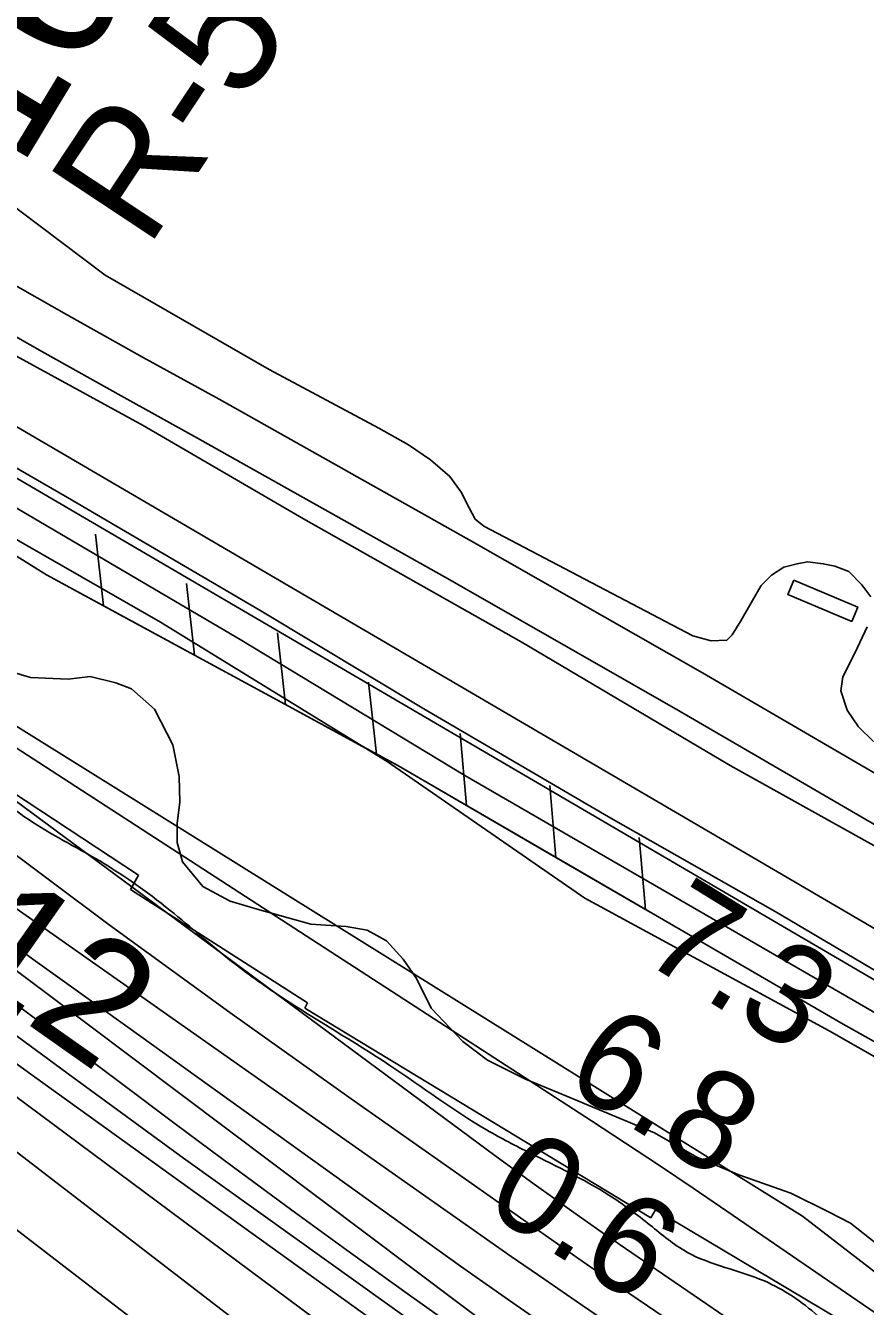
# Model space of a CAD drawing. Extents: x 3734862 to 3772949, y 391520 to 417239.
# Drawn here: x 3764747 to 3765314, y 398025 to 398891 of the extents above; entities that cross this region are included whole.
import ezdxf

# ---------------------------------------------------------------- set-up
doc = ezdxf.new("R2010")
doc.units = 0
for name, color, linetype in [('V-BLDG-OTLN', 7, 'Continuous'), ('V-FLOD-BASE', 7, 'Continuous'), ('V-LEVE-TOET', 7, 'Continuous'), ('V-RIVR-EDGE', 7, 'Continuous'), ('V-RIVR-IDEN', 7, 'Continuous'), ('V-RIVR-RANG', 7, 'Continuous'), ('V-RIVR-RANG-IDEN', 7, 'Continuous'), ('V-ROAD-CNTR', 7, 'Continuous'), ('V-RRAP-FSHR', 7, 'Continuous'), ('V-RRAP-RVMT', 7, 'Continuous'), ('V-SITE-VEGE', 7, 'Continuous'), ('V-SURV-IDEN', 7, 'Continuous'), ('V-SURV-LINE', 7, 'Continuous'), ('V-TOPO-DPTH', 7, 'Continuous'), ('V-TOPO-MAJR', 7, 'Continuous'), ('V-TOPO-MINR', 7, 'Continuous'), ('V-TOPO-WATR', 7, 'Continuous')]:
    doc.layers.add(name, color=color, linetype=linetype)

msp = doc.modelspace()

# ---------------------------------------------------------------- linework, layer by layer
at = {"layer": 'V-BLDG-OTLN'}
msp.add_lwpolyline([(3765265.95, 398515.86), (3765309.25, 398497.52), (3765305.19, 398487.94), (3765261.9, 398506.28)], close=True, dxfattribs=at)
at = {"layer": 'V-FLOD-BASE'}
msp.add_lwpolyline([(3765919.69, 397923.87), (3765784.81, 397985.29), (3765736.12, 398012.21), (3765619.99, 398078.34), (3765504.44, 398146.23), (3765380.1, 398217.04), (3765253.41, 398291.96), (3765140.8, 398355.75), (3765015.87, 398428.9), (3764905.59, 398495.04), (3764774.8, 398571.71), (3764644, 398647.2), (3764560.13, 398694.61), (3764527.87, 398714.51), (3764496.78, 398740.27), (3764392.35, 398828.69), (3764326.64, 398884.32), (3764321.95, 398887.24), (3764318.43, 398888.41), (3764313.74, 398888.41), (3764307.88, 398886.64)], dxfattribs=at)
at = {"layer": 'V-LEVE-TOET'}
for points in [[(3765336.26, 398214.64), (3765176.14, 398307.1), (3765043.58, 398383.77), (3764891.67, 398475.66), (3764737.41, 398566.38), (3764574.94, 398662.36), (3764493.99, 398717.39), (3764439.43, 398761.3), (3764323.27, 398859.67), (3764308.02, 398870.21), (3764290.2, 398882.28), (3764276.7, 398899.85), (3764221.55, 398947.28), (3764113.59, 399048), (3763978.07, 399156.91), (3763854.3, 399242.38), (3763724.66, 399337.81), (3763588.56, 399436.16), (3763446.02, 399536.27), (3763304.06, 399635.79)], [(3764703.96, 398687.18), (3764825.96, 398620.47), (3764934.47, 398557.26), (3765081.68, 398474.16), (3765223.04, 398390.47), (3765371.43, 398307.96), (3765509.86, 398218.4), (3765656.5, 398127.67), (3765782.02, 398053.35), (3765894.62, 397998.94)]]:
    msp.add_lwpolyline(points, dxfattribs=at)
at = {"layer": 'V-RIVR-EDGE'}
msp.add_spline([(3755702.08, 404495.32), (3755757.18, 404470.77), (3755793.3, 404451.23), (3755852.47, 404424.41), (3755881.39, 404415.75), (3755906.23, 404404.38), (3755920.22, 404395.76), (3755948.67, 404379.41), (3755958.16, 404378.93), (3755969.01, 404378), (3755990.69, 404368.45), (3756022.75, 404350.29), (3756054.82, 404336.64), (3756079.66, 404323.02), (3756103.59, 404309.39), (3756144.23, 404288.04), (3756167.69, 404268.99), (3756188.91, 404253.57), (3756231.36, 404233.11), (3756271.56, 404217.19), (3756299.11, 404203.1), (3756403.01, 404163.51), (3756460.37, 404140.31), (3756508.69, 404114.87), (3756530.82, 404103.96), (3756588.18, 404078.04), (3756639.21, 404052.15), (3756694.29, 404019.45), (3756726.8, 403998.12), (3756735.82, 403989.06), (3756740.32, 403979.55), (3756740.3, 403973.22), (3756740.74, 403967.79), (3756747.5, 403960.54), (3756759.69, 403953.73), (3756786.34, 403941.46), (3756814.34, 403929.18), (3756864.47, 403904.64), (3756889.32, 403895.98), (3756899.72, 403897.32), (3756908.33, 403901.82), (3756919.18, 403901.34), (3756933.18, 403894.07), (3756945.83, 403892.68), (3756956.23, 403893.11), (3756962.12, 403897.16), (3756970.71, 403896.69), (3756978.39, 403894.41), (3756992.41, 403894.83), (3757002.82, 403897.51), (3757019.1, 403901.54), (3757027.7, 403901.52), (3757034.02, 403901.05), (3757036.27, 403896.53), (3757036.71, 403891.1), (3757038.5, 403883.41), (3757046.62, 403874.34), (3757060.62, 403866.17), (3757076.41, 403853.92), (3757104.39, 403831.25), (3757122.44, 403816.73), (3757145.47, 403804.47), (3757165.34, 403796.73), (3757181.6, 403787.2), (3757194.24, 403777.67), (3757213.65, 403765.41), (3757229.9, 403756.33), (3757251.58, 403745.88), (3757266.49, 403741.32), (3757283.2, 403734.49), (3757308.94, 403720.87), (3757360.42, 403694.06), (3757393.83, 403670.92), (3757429.96, 403657.26), (3757461.59, 403645.43), (3757505.4, 403628.14), (3757548.31, 403610.4), (3757591.66, 403587.23), (3757649.45, 403552.27), (3757711.75, 403512.78), (3757753.76, 403493.23), (3757766.86, 403487.78), (3757773.19, 403487.76), (3757785.86, 403494.06), (3757794.45, 403494.04), (3757803.49, 403489.49), (3757807.08, 403480.89), (3757810.64, 403456.02), (3757814.23, 403447.87), (3757826.42, 403436.99), (3757854.41, 403422.9), (3757930.26, 403373.88), (3757975.85, 403342.57), (3758005.19, 403323.5), (3758062.07, 403286.74), (3758092.31, 403263.6), (3758175.82, 403209.59), (3758234.51, 403169.2), (3758283.7, 403133.81), (3758328.84, 403103.41), (3758399.23, 403041.74), (3758421.79, 403023.15), (3758438.05, 403017.68), (3758463.83, 403017.62), (3758491.43, 403026.14), (3758504.53, 403022.04), (3758513.56, 403014.33), (3758513.99, 403006.19), (3758499.95, 402997.18), (3758498.12, 402989.95), (3758502.16, 402978.18), (3758510.73, 402969.57), (3758522.02, 402962.76), (3758545.05, 402948.69), (3758582.07, 402926.89), (3758650.23, 402878.79), (3758697.61, 402840.7), (3758721.52, 402820.29), (3758740.94, 402809.39), (3758782.02, 402784.87), (3758831.24, 402755.36), (3758902.12, 402711.78), (3758960.36, 402675.46), (3759018.58, 402634.62), (3759069.59, 402599.68), (3759134.59, 402553.4), (3759185.57, 402508.06), (3759223.48, 402478.12), (3759262.29, 402448.18), (3759321.41, 402402.37), (3759371.51, 402366.07), (3759431.54, 402323.42), (3759463.59, 402300.28), (3759488.86, 402281.68), (3759576.89, 402222.68), (3759626.99, 402186.84), (3759672.12, 402153.72), (3759778.21, 402087.44), (3759832.83, 402050.68), (3759873, 402019.38), (3759909.55, 401989.45), (3760050.81, 401883.75), (3760100.02, 401850.16), (3760145.61, 401819.31), (3760185.77, 401788.01), (3760211.95, 401766.69), (3760254.82, 401734.48), (3760285.51, 401709.08), (3760303.12, 401700.45), (3760325.25, 401691.35), (3760352.78, 401671.39), (3760391.14, 401641), (3760430.41, 401611.96), (3760461.55, 401590.18), (3760536.95, 401542.97), (3760582.99, 401510.76), (3760602.85, 401495.79), (3760629.02, 401477.18), (3760672.36, 401449.49), (3760711.19, 401426.79), (3760818.61, 401347.85), (3760872.33, 401310.64), (3760925.58, 401271.62), (3760948.6, 401251.67), (3761039.76, 401181.81), (3761107.02, 401135.52), (3761151.7, 401104.67), (3761172.93, 401093.31), (3761186.03, 401090.57), (3761199.15, 401092.79), (3761219.51, 401099.07), (3761228.11, 401099.5), (3761233.52, 401095.42), (3761236.67, 401087.73), (3761236.64, 401077.78), (3761228.47, 401063.78), (3761223.03, 401057.47), (3761223.01, 401049.33), (3761228.86, 401039.37), (3761242.39, 401026.67), (3761254.14, 401021.67), (3761266.79, 401018.47), (3761292.52, 401001.68), (3761317.34, 400980.37), (3761342.15, 400955.44), (3761463.07, 400853.4), (3761509.99, 400812.14), (3761550.15, 400777.68), (3761585.34, 400746.84), (3761681.47, 400674.26), (3761756.4, 400618.91), (3761817.77, 400572.19), (3761878.26, 400530.44), (3761996.49, 400436.55), (3762057.42, 400389.83), (3762104.8, 400352.63), (3762156.25, 400313.17), (3762204.54, 400277.33), (3762245.17, 400247.84), (3762291.65, 400210.19), (3762325.94, 400182.07), (3762356.18, 400159.84), (3762404.02, 400123.55), (3762432.9, 400101.32), (3762455.49, 400091.32), (3762473.53, 400075.9), (3762512.34, 400044.16), (3762551.6, 400012.41), (3762593.58, 399983.82), (3762620.21, 399963.4), (3762661.74, 399937.08), (3762686.57, 399919.83), (3762793.08, 399841.35), (3762834.61, 399812.76), (3762873.44, 399790.05), (3762923.1, 399758.28), (3762956.96, 399737.4), (3762984.05, 399721.5), (3763024.22, 399693.37), (3763075.23, 399657.52), (3763115.86, 399633.91), (3763172.75, 399601.21), (3763228.74, 399568.52), (3763285.17, 399533.57), (3763344.31, 399494.08), (3763398.47, 399455.06), (3763444.06, 399421.04), (3763484.68, 399391.09), (3763603.38, 399303.08), (3763654.82, 399261.81), (3763661.14, 399259.53), (3763667.01, 399254.54), (3763671.96, 399245.04), (3763696.33, 399224.18), (3763722.94, 399200.15), (3763745.5, 399180.2), (3763818.14, 399117.17), (3763841.61, 399099.47), (3763852.45, 399092.21), (3763858.76, 399084.06), (3763874.99, 399067.29), (3763898, 399045.98), (3763924.62, 399023.76), (3763949, 399007.87), (3763970.2, 398987.47), (3764004.03, 398952.57), (3764028.38, 398926.74), (3764056.8, 398899.54), (3764092.88, 398862.37), (3764130.77, 398826.11), (3764147.01, 398811.6), (3764152.86, 398799.83), (3764162.32, 398783.53), (3764173.58, 398768.58), (3764186.67, 398757.24), (3764206.08, 398746.34), (3764226.87, 398742.22), (3764246.29, 398733.58), (3764269.32, 398717.7), (3764284.2, 398703.19), (3764301.81, 398691.84), (3764323.02, 398678.23), (3764345.14, 398660.99), (3764412.35, 398596.62), (3764457.02, 398559.88), (3764502.6, 398522.69), (3764538.26, 398497.74), (3764566.26, 398486.36), (3764583.89, 398484.51), (3764604.25, 398486.27), (3764616.45, 398486.24), (3764626.39, 398481.69), (3764630.89, 398474.45), (3764636.29, 398461.32), (3764634.9, 398450.02), (3764631.72, 398441.44), (3764633.06, 398434.65), (3764636.21, 398430.12), (3764643.89, 398425.58), (3764661.06, 398421.47), (3764685.44, 398409.2), (3764715.22, 398382), (3764745.45, 398356.15), (3764793.31, 398328), (3764844.31, 398292.6), (3764885.83, 398258.14), (3764918.78, 398234.54), (3764992.82, 398187.79), (3765058.27, 398144.22), (3765088.07, 398128.32), (3765140.91, 398100.15), (3765168.89, 398079.74), (3765193.71, 398061.59), (3765246.12, 398042.02), (3765282.23, 398018.42), (3765309.74, 397989.41), (3765339.95, 397955.42), (3765361.15, 397933.67), (3765382.35, 397911.91), (3765434.69, 397867.92), (3765477.57, 397838.43), (3765508.73, 397823.88), (3765545.3, 397801.18), (3765575.54, 397778.05), (3765617.52, 397749.91), (3765653.64, 397726.31), (3765681.63, 397709.96), (3765727.23, 397684.53), (3765761.99, 397660.02), (3765771.94, 397659.55), (3765788.21, 397659.96), (3765793.64, 397658.14), (3765793.63, 397653.62), (3765785.47, 397648.66), (3765785.47, 397645.5), (3765790.86, 397632.82), (3765800.33, 397623.76), (3765814.78, 397612.87), (3765831.94, 397605.59), (3765847.31, 397603.29), (3765858.15, 397598.75), (3765865.82, 397593.3), (3765888.84, 397576.97), (3765908.7, 397561.54), (3765918.16, 397548.41), (3765919.5, 397542.07), (3765921.3, 397536.19), (3765926.71, 397533.46), (3765933.05, 397534.35), (3765940.73, 397533.43), (3765944.79, 397530.25), (3765956.97, 397519.37), (3765987.67, 397499.85), (3766024.67, 397468.11), (3766059.41, 397438.18), (3766085.13, 397413.25), (3766102.73, 397400.09), (3766131.61, 397377.42), (3766172.69, 397350.18), (3766210.59, 397318.89), (3766264.32, 397285.3), (3766306.76, 397260.78), (3766362.73, 397220.85), (3766381.12, 397208.5)], degree=3, dxfattribs=at)
at = {"layer": 'V-ROAD-CNTR'}
for points in [[(3764722.94, 398724.48), (3764774.26, 398695.49), (3764825.72, 398666.73), (3764877.38, 398638.16), (3765048.14, 398542.14), (3765204.25, 398453.13), (3765349.06, 398368.89), (3765503.3, 398282.87), (3765646.99, 398199.77), (3765779.29, 398126.18), (3765922.48, 398050.51), (3766092.78, 397963.66)], [(3765902.81, 398026.98), (3765764.99, 398099.8), (3765632.19, 398173.68), (3765488.48, 398256.79), (3765334.21, 398342.82), (3765189.28, 398427.13), (3765033.36, 398516.03), (3764862.77, 398611.96), (3764811.14, 398640.51), (3764759.57, 398669.34), (3764708.13, 398698.39)]]:
    msp.add_lwpolyline(points, dxfattribs=at)
at = {"layer": 'V-RRAP-FSHR'}
for p, q in [((3764799.31, 398498.53), (3764793.79, 398547.05)), ((3764860.83, 398465.13), (3764855.31, 398513.65)), ((3764922.34, 398431.73), (3764916.82, 398480.24)), ((3764983.86, 398398.32), (3764978.33, 398446.84)), ((3765044.62, 398363.57), (3765040.49, 398412.23)), ((3765105.15, 398328.41), (3765101.02, 398377.07)), ((3765165.68, 398293.26), (3765161.55, 398341.91))]:
    msp.add_line(p, q, dxfattribs=at)
for points in [[(3764998.22, 398390.52), (3764760.68, 398519.52), (3764522.48, 398668.18), (3764156.84, 398982.99), (3763831.74, 399229.97), (3763537.37, 399441.78), (3763368.02, 399565.45), (3763155.93, 399717.09), (3762782.34, 399993.3), (3762479.05, 400204.22), (3762102.73, 400498.17), (3761742.79, 400796.03), (3761554.49, 400943.7), (3761225.86, 401154.8), (3760827.95, 401453.26), (3760408.26, 401760.51)], [(3763828.66, 399148.5), (3764283.79, 398756.79), (3764609.98, 398498.2), (3765271.96, 398085.75), (3765448.14, 397950), (3765966.29, 397562.89), (3766316.05, 397303.97), (3766451.05, 397209.41)], [(3764799.31, 398498.53), (3764760.68, 398519.52), (3764738.59, 398533.3)], [(3764860.83, 398465.13), (3764799.31, 398498.54)], [(3764922.34, 398431.73), (3764860.83, 398465.13)], [(3764983.86, 398398.32), (3764922.34, 398431.73)], [(3765044.62, 398363.57), (3764998.22, 398390.52), (3764983.86, 398398.32)], [(3766601.57, 397221.78), (3766586.06, 397233.5), (3766361.7, 397485.46), (3766220.77, 397673.48), (3766120.11, 397770.42), (3765775.08, 397948.91), (3765297.8, 398216.51), (3764998.22, 398390.52)], [(3765105.15, 398328.41), (3765044.62, 398363.57)], [(3765165.68, 398293.26), (3765105.15, 398328.41)], [(3765176.71, 398286.84), (3765165.67, 398293.26)]]:
    msp.add_lwpolyline(points, dxfattribs=at)
at = {"layer": 'V-RRAP-RVMT'}
for p, q in [((3764691.68, 398402.77), (3764822.88, 398316.32)), ((3764822.88, 398316.32), (3764817.52, 398306.74)), ((3764817.52, 398306.74), (3764937.16, 398230.01)), ((3764937.16, 398230.01), (3764935.4, 398226.56)), ((3764935.4, 398226.56), (3765169.3, 398084.71)), ((3765169.3, 398084.71), (3765172.5, 398090.11)), ((3765172.5, 398090.11), (3765308.65, 398008.95))]:
    msp.add_line(p, q, dxfattribs=at)
at = {"layer": 'V-SITE-VEGE'}
for points in [[(3765318.02, 398504.53), (3765312.08, 398512.83), (3765303.18, 398521.71), (3765293.69, 398525.26), (3765285.98, 398527.03), (3765275.31, 398528.2), (3765268.2, 398527.01), (3765259.31, 398524.63), (3765251.01, 398519.29), (3765243.9, 398512.17), (3765237.99, 398502.08), (3765230.29, 398488.44), (3765224.37, 398478.95), (3765220.82, 398475.39), (3765210.15, 398474.79), (3765197.7, 398478.33), (3765056.53, 398552.3), (3765050.6, 398557.04), (3765046.44, 398564.74), (3765041.09, 398575.41), (3765033.38, 398586.07), (3765020.33, 398597.32), (3765005.5, 398607.39), (3764985.33, 398618.63), (3764911.19, 398658.28), (3764800.27, 398722.2), (3764638.9, 398843.58)], [(3764251.87, 398782.17), (3764251.26, 398795.24), (3764253.63, 398803.55), (3764261.93, 398816.63), (3764272.61, 398828.52), (3764280.92, 398835.06), (3764284.48, 398836.84), (3764289.83, 398834.48), (3764407.5, 398752.03), (3764562.01, 398650.03), (3764677.29, 398579.47), (3764837.73, 398487.56), (3764991.05, 398393.28), (3765124.76, 398300.76), (3765289.95, 398211.24), (3765409.39, 398143.05), (3765564.49, 398044.02), (3765706.52, 397954.48), (3765828.91, 397906.49), (3765859.81, 397892.27), (3765872.88, 397880.4), (3765881.81, 397860.8), (3765881.83, 397845.37), (3765878.87, 397830.52)], [(3765319.89, 398406.71), (3765309.8, 398416.78), (3765302.08, 398428.04), (3765297.92, 398441.08), (3765299.1, 398450.57), (3765307.38, 398466.58), (3765315.66, 398484.37)], [(3765321.57, 398067.54), (3765304.33, 398081.19), (3765289.47, 398088.89), (3765263.93, 398101.34), (3765228.87, 398113.78), (3765200.35, 398125.63), (3765171.83, 398142.23), (3765106.48, 398169.49), (3765084.49, 398178.38), (3765058.94, 398191.42), (3765042.3, 398203.87), (3765020.9, 398226.42), (3765010.79, 398246.61), (3765001.87, 398259.66), (3764990.57, 398272.12), (3764977.5, 398279.24), (3764963.24, 398281.6), (3764939.48, 398283.36), (3764903.25, 398293.42), (3764884.83, 398298.75), (3764866.41, 398308.83), (3764852.73, 398325.44), (3764849.16, 398338.51), (3764849.14, 398351.57), (3764850.91, 398365.83), (3764850.3, 398383.05), (3764846.12, 398404.43), (3764833.63, 398428.76), (3764818.18, 398442.41), (3764807.48, 398446.56), (3764790.25, 398450.7), (3764775.41, 398448.9), (3764749.87, 398450.06), (3764725.51, 398457.17)]]:
    msp.add_lwpolyline(points, dxfattribs=at)
at = {"layer": 'V-SURV-LINE'}
for points in [[(3764569.28, 398719.71), (3765745.45, 398031.68)], [(3765730.3, 398005.79), (3764554.13, 398693.82)]]:
    msp.add_lwpolyline(points, dxfattribs=at)
at = {"layer": 'V-TOPO-DPTH'}
for points in [[(3764499.94, 398544.15), (3765063.81, 398126.9), (3765077.07, 398117.16), (3765090.38, 398107.49), (3765103.77, 398097.91), (3765117.2, 398088.4), (3765140.36, 398072.15), (3765142.25, 398070.82), (3765144.15, 398069.5), (3765146.05, 398068.19), (3765147.96, 398066.88), (3765278.68, 397977.46)], [(3764441.97, 398475.94), (3765071.49, 398002.99)], [(3764441.97, 398475.94), (3765071.49, 398002.99)], [(3765073.95, 397984.1), (3765006.27, 398032.33), (3764966.36, 398061), (3764926.6, 398089.86), (3764887.06, 398119.02), (3764847.67, 398148.37), (3764446.51, 398449.65)], [(3765073.95, 397984.1), (3765006.27, 398032.33), (3764966.36, 398061), (3764926.6, 398089.86), (3764887.06, 398119.02), (3764847.67, 398148.37), (3764446.51, 398449.65)], [(3766349.94, 397208.09), (3766278.64, 397256.63), (3765850.67, 397545.25), (3765820.62, 397565.41), (3765790.5, 397585.45), (3765760.27, 397605.34), (3765729.97, 397625.11), (3765655.75, 397673.28), (3765588.35, 397717.17), (3765521.05, 397761.21), (3765453.9, 397805.46), (3765386.83, 397849.85), (3765163.07, 397998.48), (3765140.92, 398013.32), (3765118.84, 398028.28), (3765096.89, 398043.4), (3765075.01, 398058.65), (3764529.77, 398441.72)], [(3766349.94, 397208.09), (3766278.64, 397256.63), (3765850.67, 397545.25), (3765820.62, 397565.41), (3765790.5, 397585.45), (3765760.27, 397605.34), (3765729.97, 397625.11), (3765655.75, 397673.28), (3765588.35, 397717.17), (3765521.05, 397761.21), (3765453.9, 397805.46), (3765386.83, 397849.85), (3765163.07, 397998.48), (3765140.92, 398013.32), (3765118.84, 398028.28), (3765096.89, 398043.4), (3765075.01, 398058.65), (3764529.77, 398441.72)], [(3764704.19, 398234.41), (3764778.63, 398179.51), (3764853.45, 398125.13), (3764928.53, 398071.1), (3765055.54, 397980.38)], [(3764704.19, 398234.41), (3764778.63, 398179.51), (3764853.45, 398125.13), (3764928.53, 398071.1), (3765055.54, 397980.38)]]:
    msp.add_lwpolyline(points, dxfattribs=at)
at = {"layer": 'V-TOPO-MAJR'}
msp.add_lwpolyline([(3766164.7, 397205.68), (3766164.18, 397206.06), (3766058.5, 397284.2), (3765796.09, 397479.4), (3765773.08, 397496.21), (3765749.89, 397512.74), (3765726.4, 397528.86), (3765702.73, 397544.72), (3765678.89, 397560.33), (3765655.01, 397575.89), (3765631.09, 397591.37), (3765607.13, 397606.8), (3765108.21, 397927.03), (3765089.81, 397939.04), (3765071.55, 397951.25), (3765053.48, 397963.75), (3765035.54, 397976.43), (3764752.63, 398179.95), (3764693.25, 398222.93)], dxfattribs=at)
at = {"layer": 'V-TOPO-MINR'}
for points in [[(3765071.49, 398002.99), (3764441.97, 398475.94)], [(3765073.95, 397984.1), (3765006.27, 398032.33), (3764966.36, 398061), (3764926.6, 398089.86), (3764887.06, 398119.02), (3764847.67, 398148.37), (3764446.51, 398449.65)], [(3766349.94, 397208.09), (3766278.64, 397256.63), (3765850.67, 397545.25), (3765820.62, 397565.41), (3765790.5, 397585.45), (3765760.27, 397605.34), (3765729.97, 397625.11), (3765655.75, 397673.28), (3765588.35, 397717.17), (3765521.05, 397761.21), (3765453.9, 397805.46), (3765386.83, 397849.85), (3765163.07, 397998.48), (3765140.92, 398013.32), (3765118.84, 398028.28), (3765096.89, 398043.4), (3765075.01, 398058.65), (3764529.77, 398441.72)], [(3764993.2, 397934.91), (3764384.94, 398402.65)], [(3766460.76, 397209.53), (3766410.66, 397251.45), (3766331.81, 397314.78), (3766251.1, 397375.7), (3766169.14, 397435.03), (3765891.34, 397629.84), (3765863.96, 397648.96), (3765836.53, 397668), (3765809.03, 397686.94), (3765781.47, 397705.8), (3765710.36, 397754.27), (3765647.23, 397797.34), (3765584.12, 397840.43), (3765521.03, 397883.57), (3765457.96, 397926.73), (3765220.71, 398089.22), (3765197.96, 398104.67), (3765175.15, 398120.01), (3765152.21, 398135.17), (3765129.2, 398150.22), (3764731.19, 398408.46)], [(3766370.47, 397208.36), (3765852.77, 397560.8), (3765825.2, 397579.51), (3765797.61, 397598.18), (3765769.96, 397616.77), (3765742.28, 397635.32), (3765714.6, 397653.86), (3765686.95, 397672.44), (3765659.33, 397691.08), (3765631.75, 397709.77), (3765155.2, 398033.25), (3765143.46, 398041.26), (3765131.75, 398049.31), (3765120.08, 398057.41), (3765108.43, 398065.55), (3764966.67, 398165.13), (3764884.57, 398223.64), (3764803, 398282.88), (3764722.24, 398343.22)], [(3766101.35, 397204.86), (3766085.14, 397216.4), (3766013.55, 397267.54), (3765942.04, 397318.79), (3765870.58, 397370.1), (3765762.76, 397447.66), (3765745.2, 397460.18), (3765727.57, 397472.61), (3765709.85, 397484.89), (3765692.05, 397497.08), (3765401.02, 397694.77), (3765343.78, 397733.75), (3765286.59, 397772.81), (3765229.49, 397812.01), (3765172.44, 397851.29), (3765114.7, 397891.14), (3765086.68, 397910.7), (3765058.8, 397930.46), (3765031.12, 397950.5), (3765003.58, 397970.75), (3764544.5, 398311.94)], [(3766329.37, 397207.82), (3766240.15, 397269.02), (3766135.69, 397339.68), (3765834.18, 397541.46), (3765809.29, 397557.98), (3765784.3, 397574.35), (3765759.19, 397590.52), (3765733.98, 397606.55), (3765421.76, 397803.33), (3765368.81, 397836.82), (3765315.92, 397870.42), (3765263.14, 397904.18), (3765210.43, 397938.04), (3765171.68, 397963.02), (3765138.56, 397984.72), (3765105.65, 398006.75), (3765073.08, 398029.26), (3765040.74, 398052.1), (3764815.59, 398213.54), (3764751.54, 398259.71), (3764687.64, 398306.09)], [(3765055.54, 397980.38), (3764928.53, 398071.1), (3764853.45, 398125.13), (3764778.63, 398179.51), (3764704.19, 398234.41)], [(3765904.53, 397202.29), (3765869.37, 397226.78), (3765829.28, 397255.03), (3765789.44, 397283.64), (3765749.76, 397312.47), (3765730.38, 397326.69), (3765700.58, 397348.67), (3765670.86, 397370.76), (3765641.26, 397393.02), (3765611.75, 397415.38), (3765445.61, 397542.03), (3765374.57, 397595.98), (3765303.41, 397649.78), (3765232.06, 397703.34), (3765160.6, 397756.73), (3765054.89, 397835.42), (3765036.23, 397849.39), (3765017.61, 397863.43), (3764999.06, 397877.55), (3764980.55, 397891.74), (3764856.16, 397987.65), (3764775.43, 398049.75), (3764694.6, 398111.73)]]:
    msp.add_lwpolyline(points, dxfattribs=at)
at = {"layer": 'V-TOPO-WATR'}
msp.add_lwpolyline([(3765278.68, 397977.46), (3765147.96, 398066.88), (3765146.05, 398068.19), (3765144.15, 398069.5), (3765142.25, 398070.82), (3765140.36, 398072.15), (3765117.2, 398088.4), (3765103.77, 398097.91), (3765090.38, 398107.49), (3765077.07, 398117.16), (3765063.81, 398126.9), (3764499.94, 398544.15)], dxfattribs=at)

# ---------------------------------------------------------------- texts
at = {"layer": 'V-RIVR-IDEN'}
msp.add_text('2012', height=83, rotation=324.8513, dxfattribs=at).set_placement((3764593.63, 398324.23))
at = {"layer": 'V-RIVR-RANG'}
for s, p in [('7.3', (3765160.9, 398260.27)), ('7.3', (3765160.9, 398260.27)), ('7.3', (3765160.9, 398260.27)), ('6.8', (3765108.57, 398175.06)), ('6.8', (3765108.57, 398175.06)), ('6.8', (3765108.57, 398175.06)), ('0.6', (3765054.67, 398090.81)), ('0.6', (3765054.67, 398090.81)), ('0.6', (3765054.67, 398090.81))]:
    msp.add_text(s, height=67, rotation=328.29833, dxfattribs=at).set_placement(p)
at = {"layer": 'V-RIVR-RANG-IDEN'}
msp.add_text('R-50.0', height=83, rotation=56.49024, dxfattribs=at).set_placement((3764828.79, 398739.19))
at = {"layer": 'V-SURV-IDEN'}
msp.add_text('1637+73.9', height=100, rotation=58.9125, dxfattribs=at).set_placement((3764742.59, 398793.14))

doc.saveas('drawing.dxf')
